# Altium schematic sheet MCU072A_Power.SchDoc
size 431 x 279 mm; Date: Not shown in title block; ApprovedBy: Not shown in title block; CheckedBy: Not shown in title block; Author: Not shown in title block; CompanyName: Not shown in title block; DrawnBy: Cody Watkins; Engineer: Not shown in title block; Organization: Not shown in title block; Address1: Not shown in title block; Address2: Not shown in title block; Address3: Not shown in title block; Address4: Not shown in title block; DocumentNumber: 3; Revision: Use project parameter SCH_Rev; SheetNumber: 3; SheetTotal: 7; PageSetup: Record=PageOptions¦CenterHorizontal=True¦CenterVertical=True¦PrintScale=1.00¦XCorrection=1.00¦YCorrection=1.00¦PrintKind=0¦BorderSize=5000000¦LeftOffset=0¦BottomOffset=0¦Orientation=2¦PaperLength=1000¦PaperWidth=1000¦Scale=100¦PaperSource=15¦PrintQuality=600¦MediaType=1¦DitherType=10¦PaperKind=Letter¦PrintScaleMode=1
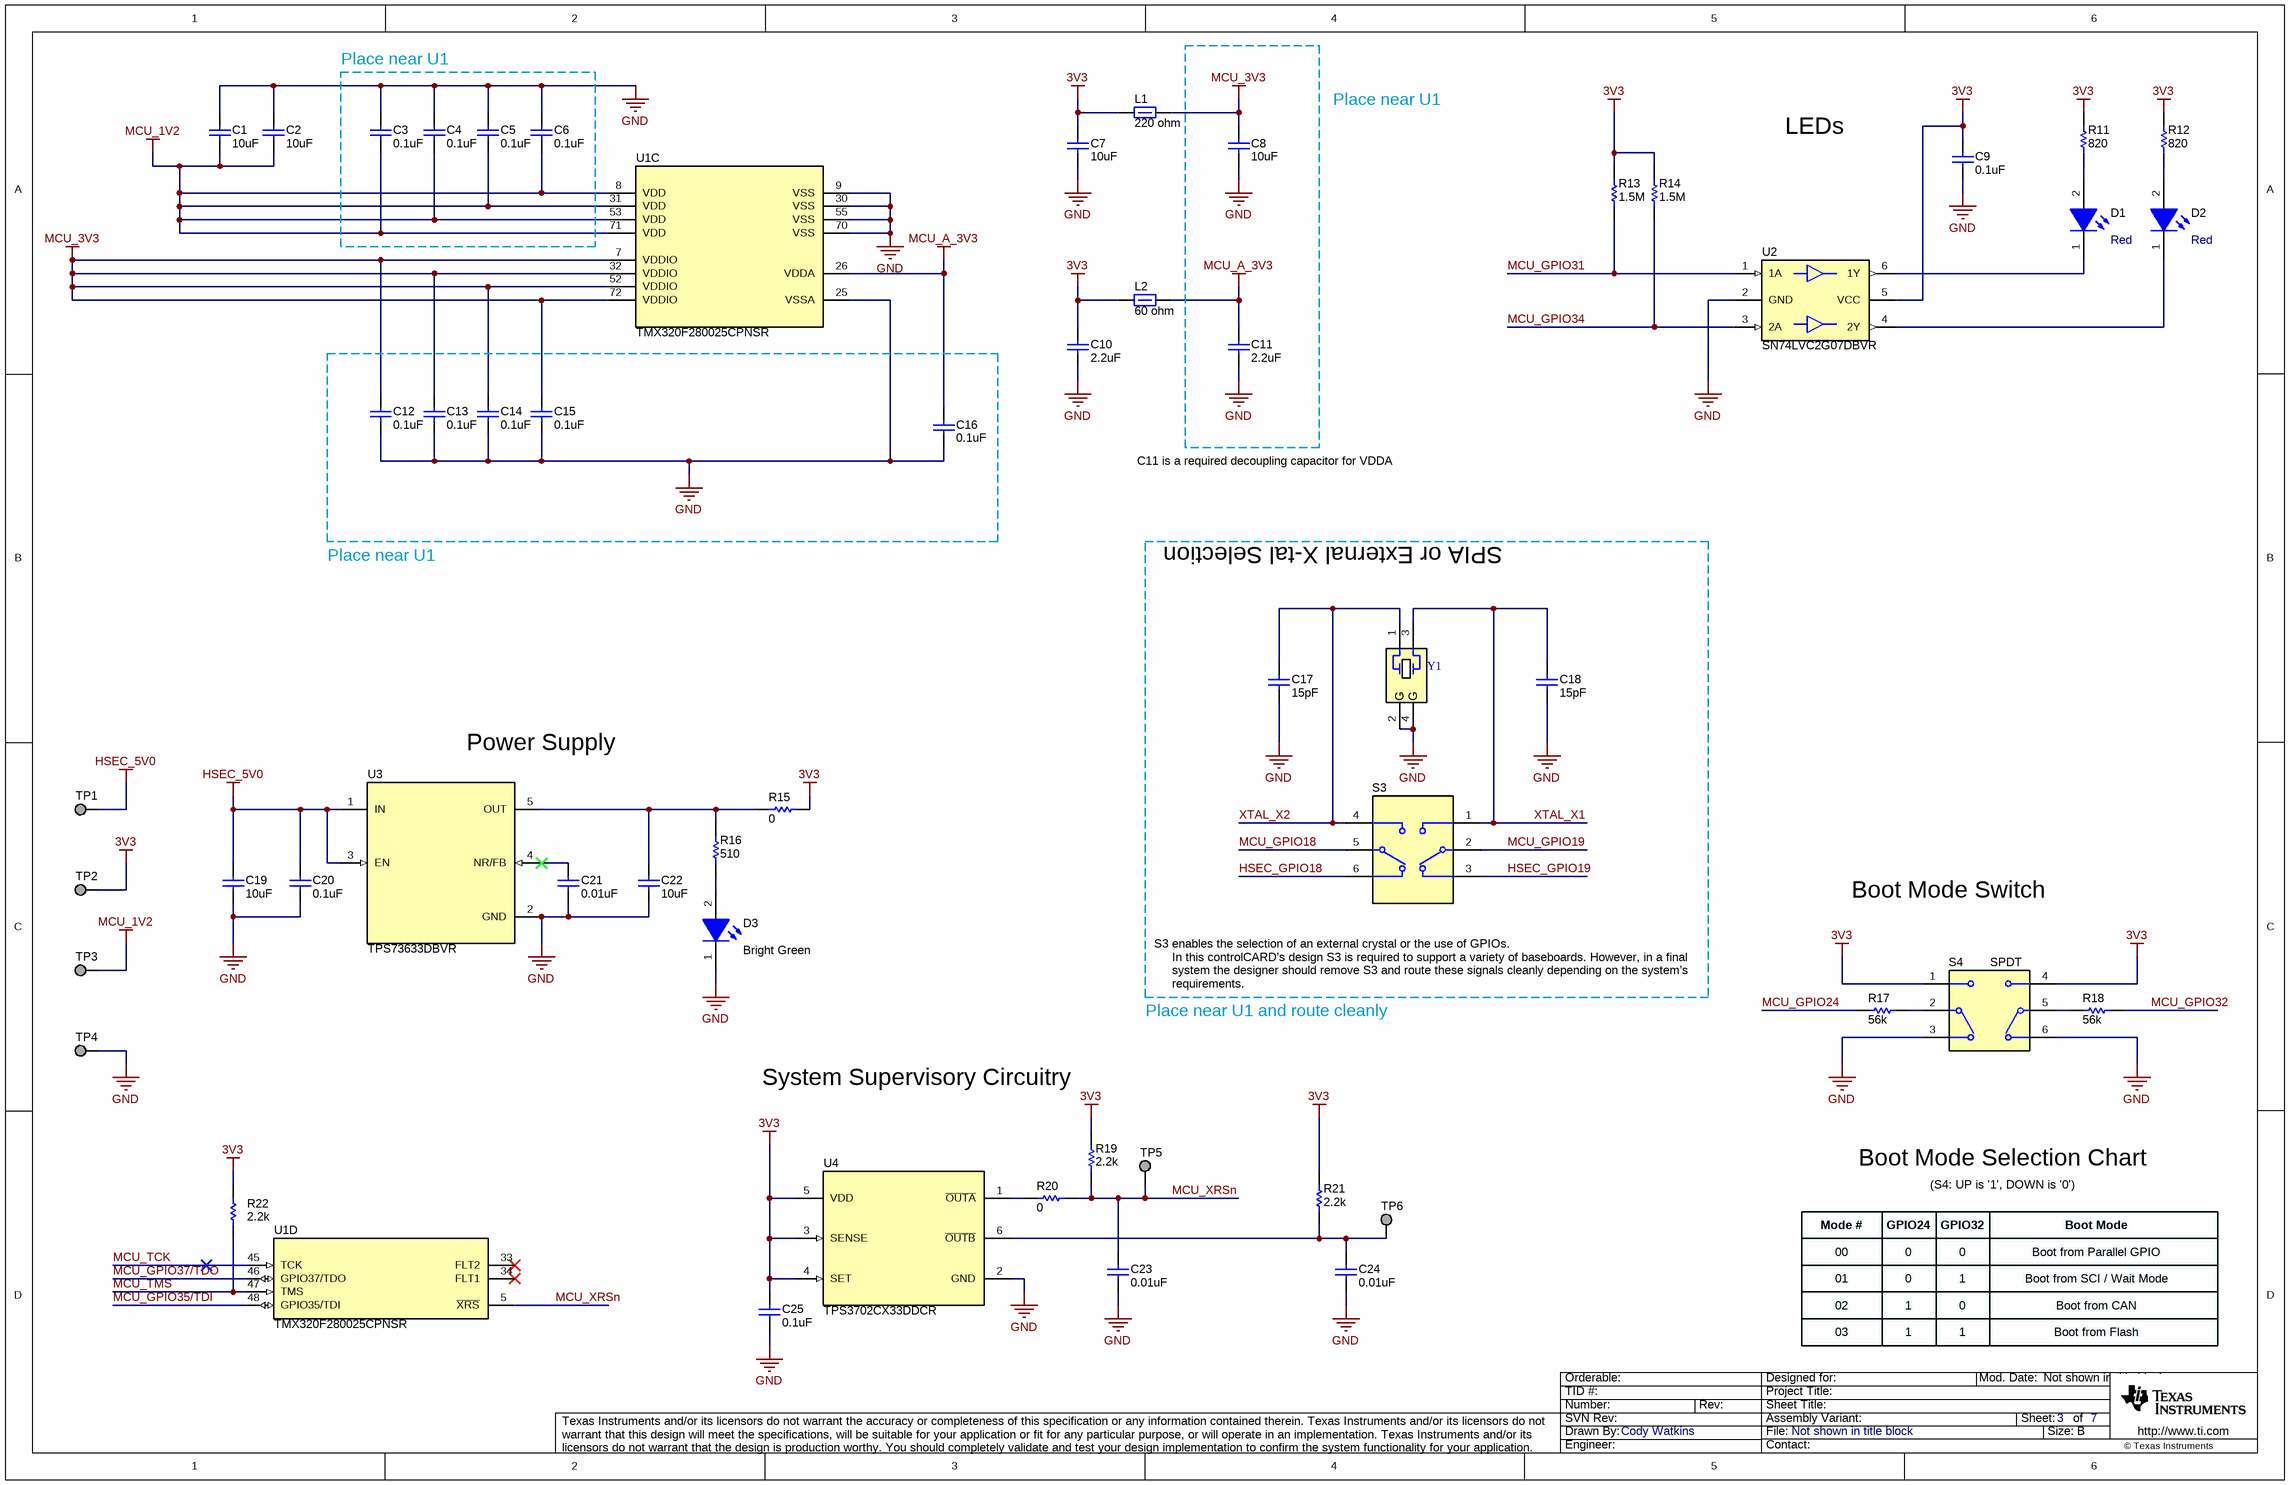
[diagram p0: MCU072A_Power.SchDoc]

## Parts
C1  ValueDisplayed: 10uF  [0603]  (hidden comment: GRM188R61A106ME69D)
C2  ValueDisplayed: 10uF  [0603]  (hidden comment: GRM188R61A106ME69D)
C3  ValueDisplayed: 0.1uF  [0402]  (hidden comment: 885012105010)
C4  ValueDisplayed: 0.1uF  [0402]  (hidden comment: 885012105010)
C5  ValueDisplayed: 0.1uF  [0402]  (hidden comment: 885012105010)
C6  ValueDisplayed: 0.1uF  [0402]  (hidden comment: 885012105010)
C7  ValueDisplayed: 10uF  [0805_HV]  (hidden comment: LMK212ABJ106KG-T)
C8  ValueDisplayed: 10uF  [0603]  (hidden comment: GRM188R61A106ME69D)
C9  ValueDisplayed: 0.1uF  [0402]  (hidden comment: 885012105010)
C10  ValueDisplayed: 2.2uF  [0603]  (hidden comment: CGA3E3X5R1A225K080AB)
C11  ValueDisplayed: 2.2uF  [0603]  (hidden comment: CGA3E3X5R1A225K080AB)
C12  ValueDisplayed: 0.1uF  [0402]  (hidden comment: 885012105010)
C13  ValueDisplayed: 0.1uF  [0402]  (hidden comment: 885012105010)
C14  ValueDisplayed: 0.1uF  [0402]  (hidden comment: 885012105010)
C15  ValueDisplayed: 0.1uF  [0402]  (hidden comment: 885012105010)
C16  ValueDisplayed: 0.1uF  [0402]  (hidden comment: 885012105010)
C17  ValueDisplayed: 15pF  [0402]  (hidden comment: 885012005056)
C18  ValueDisplayed: 15pF  [0402]  (hidden comment: 885012005056)
C19  ValueDisplayed: 10uF  [0603]  (hidden comment: GRM188R61A106ME69D)
C20  ValueDisplayed: 0.1uF  [0402]  (hidden comment: 885012105010)
C21  ValueDisplayed: 0.01uF  [0402]  (hidden comment: 0402ZC103KAT2A)
C22  ValueDisplayed: 10uF  [0603]  (hidden comment: GRM188R61A106ME69D)
C23  ValueDisplayed: 0.01uF  [0402]  (hidden comment: 0402ZC103KAT2A)
C24  ValueDisplayed: 0.01uF  [0402]  (hidden comment: 0402ZC103KAT2A)
C25  ValueDisplayed: 0.1uF  [0402]  (hidden comment: 885012105010)
D1  value Red  [WL-SMCW_RED_0805]  (hidden comment: 150080SS75000)
D2  value Red  [WL-SMCW_RED_0805]  (hidden comment: 150080SS75000)
D3  value Bright Green  [WL-SMCW_Green_0805]  (hidden comment: 150080VS75000)
L1  value 220 ohm  [0805_HV]  (hidden comment: BLM21PG221SN1D)
L2  value 60 ohm  [0805_HV]  (hidden comment: BKP2125HS600-T)
R11  ValueDisplayed: 820  [0402]  (hidden comment: CRCW0402820RJNED)
R12  ValueDisplayed: 820  [0402]  (hidden comment: CRCW0402820RJNED)
R13  ValueDisplayed: 1.5M  [0402]  (hidden comment: CRCW04021M50JNED)
R14  ValueDisplayed: 1.5M  [0402]  (hidden comment: CRCW04021M50JNED)
R15  ValueDisplayed: 0  [0805_HV]  (hidden comment: CRCW08050000Z0EA)
R16  ValueDisplayed: 510  [0402]  (hidden comment: CRCW0402510RJNED)
R17  ValueDisplayed: 56k  [0402]  (hidden comment: CRCW040256K0JNED)
R18  ValueDisplayed: 56k  [0402]  (hidden comment: CRCW040256K0JNED)
R19  ValueDisplayed: 2.2k  [0402]  (hidden comment: CRCW04022K20JNED)
R20  ValueDisplayed: 0  [0402]  (hidden comment: CRCW04020000Z0ED)
R21  ValueDisplayed: 2.2k  [0402]  (hidden comment: CRCW04022K20JNED)
R22  ValueDisplayed: 2.2k  [0402]  (hidden comment: CRCW04022K20JNED)
S3  CAS-220TA  [SW_CAS-220TA]  (value not drawn)
S4  Circuit: SPDT  [SW_CAS-D20TA]  (hidden comment: CAS-D20TA)
TP1  TESTPOINT  [TP_50MIL-25MILHOLE]  (value not drawn)  (no BOM)
TP2  TESTPOINT  [TP_50MIL-25MILHOLE]  (value not drawn)  (no BOM)
TP3  TESTPOINT  [TP_50MIL-25MILHOLE]  (value not drawn)  (no BOM)
TP4  TESTPOINT  [TP_50MIL-25MILHOLE]  (value not drawn)  (no BOM)
TP5  TESTPOINT  [TP_50MIL-25MILHOLE]  (value not drawn)  (no BOM)
TP6  TESTPOINT  [TP_50MIL-25MILHOLE]  (value not drawn)  (no BOM)
U1  TMX320F280025CPNSR  [PN0080A_N]  (parts C,D of 4)
U2  SN74LVC2G07DBVR  [DBV0006A_N]
U3  TPS73633DBVR  [DBV0005A_N]
U4  TPS3702CX33DDCR  [DDC0006A_N]
Y1  ECS-200-18-30B-AGN-TR  [ECS_ECX-53B]  (value not drawn)

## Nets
3V3: C7.2 C9.1 C10.2 C25.1 L1.1 L2.1 R11.2 R12.2 R13.2 R14.2 R15.2 R19.2 R21.2 R22.2 S4.1 S4.4 TP2.1 U2.5(VCC) U4.3(SENSE) U4.4(SET) U4.5(VDD)
GND: C1.2 C2.2 C3.1 C4.1 C5.1 C6.1 C7.1 C8.2 C9.2 C10.1 C11.1 C12.2 C13.2 C14.2 C15.2 C16.2 C17.2 C18.2 C19.2 C20.2 C21.1 C22.1 C23.1 C24.1 C25.2 D3.1(K) S4.3 S4.6 TP4.1 U1.9(VSS) U1.25(VSSA) U1.30(VSS) U1.55(VSS) U1.70(VSS) U2.2(GND) U3.2(GND) U4.2(GND) Y1.2(GND) Y1.4(GND)
HSEC_5V0: C19.1 C20.1 TP1.1 U3.1(IN) U3.3(EN)
MCU_1V2: C1.1 C2.1 C3.2 C4.2 C5.2 C6.2 TP3.1 U1.8(VDD) U1.31(VDD) U1.53(VDD) U1.71(VDD)
MCU_3V3: C8.1 C12.1 C13.1 C14.1 C15.1 L1.2 U1.7(VDDIO) U1.32(VDDIO) U1.52(VDDIO) U1.72(VDDIO)
MCU_A_3V3: C11.2 C16.1 L2.2 U1.26(VDDA)
HSEC_GPIO18: S3.6
HSEC_GPIO19: S3.3
MCU_GPIO18: S3.5
MCU_GPIO19: S3.2
MCU_GPIO24: R17.2
MCU_GPIO31: R13.1 U2.1(1A)
MCU_GPIO32: R18.1
MCU_GPIO34: R14.1 U2.3(2A)
MCU_GPIO35/TDI: U1.48(GPIO35/TDI)
MCU_GPIO37/TDO: U1.46(GPIO37/TDO)
MCU_TCK: U1.45(TCK)
MCU_TMS: R22.1 U1.47(TMS)
MCU_XRSn: C23.2 R19.1 R20.2 TP5.1 U1.5(~{XRS})
XTAL_X1: C18.1 S3.1 Y1.3
XTAL_X2: C17.1 S3.4 Y1.1
NetC21_2: C21.2 U3.4(NR/FB)
NetC22_2: C22.2 R15.1 R16.2 U3.5(OUT)
NetC24_2: C24.2 R21.1 TP6.1 U4.6(~{OUTB})
NetD1_1: D1.1(K) U2.6(1Y)
NetD1_2: D1.2(A) R11.1
NetD2_1: D2.1(K) U2.4(2Y)
NetD2_2: D2.2(A) R12.1
NetD3_2: D3.2(A) R16.1
NetR17_1: R17.1 S4.2(C)
NetR18_2: R18.2 S4.5(C)
NetR20_1: R20.1 U4.1(~{OUTA})

Not connected (* = marked no-connect by the designer): U1 33(FLT2)* 34(FLT1)*

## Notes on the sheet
- Place near U1
- LEDs
- C11 is a required decoupling capacitor for VDDA
- SPIA or External X-tal Selection
- Power Supply
- Boot Mode Switch
- In this controlCARD’s design S3 is required to support a variety of baseboards. However, in a final
- system the designer should remove S3 and route these signals cleanly depending on the system’s
- S3 enables the selection of an external crystal or the use of GPIOs.
- Place near U1 and route cleanly
- requirements.
- System Supervisory Circuitry
- Boot Mode Selection Chart
- Mode #
- GPIO24
- GPIO32
- (S4: UP is '1', DOWN is '0')
- Boot Mode
- 00
- 01
- 02
- 0
- 1
- Boot from Parallel GPIO
- Boot from SCI / Wait Mode
- Boot from CAN
- 03
- Boot from Flash

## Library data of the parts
C1 C2 C8 C19 C22 = CMP-0007318-5: CAP, CERM, 10 uF, 10 V, +/- 20%, X5R, 0603; Manufacturer: MuRata; Polarized: N; Value: 10uF; U/M: EA; Cap_F: 10µF; Value1: Unknown; VDC_V: 10V; TaMin_C: -55°C; TaMax_C: 85°C; AEC Category: Q200; SizeArea_mm2: 1.28; SizeAreaWB_mm2: 4.68; SizeX_mm: 1.6; SizeY_mm: 0.8; SizeZ_mm: 1
C3-C6 C12-C16 = CMP-0006221-2: CAP, CERM, 0.1 uF, 10 V, +/- 20%, X5R, 0402; Manufacturer: Wurth Elektronik; Polarized: N; Value: 0.1uF; U/M: EA; Cap_F: 100nF; Value1: Unknown; VDC_V: 10V; TaMin_C: -55°C; TaMax_C: 85°C; SizeArea_mm2: 0.5; SizeAreaWB_mm2: 3; SizeX_mm: 1; SizeZ_mm: 0.6; AEC Category: Q200
C7 = CMP-0008395-2: CAP, CERM, 10 uF, 10 V, +/- 10%, X5R, 0805; Manufacturer: Taiyo Yuden; Polarized: N; Value: 10uF; U/M: EA; Cap_F: 10µF; Value1: Unknown; VDC_V: 10V; TaMin_C: -55°C; TaMax_C: 85°C; Cap_Case: 0805; AEC Category: Q200; SizeArea_mm2: 2.5; SizeAreaWB_mm2: 6.75; SizeX_mm: 2; SizeY_mm: 1.25; SizeZ_mm: 1.45
C9 C20 C25 = CMP-0006221-2: CAP, CERM, 0.1 uF, 10 V, +/- 20%, X5R, 0402; Manufacturer: Wurth Elektronik; Polarized: N; Value: 0.1uF; U/M: EA; Cap_F: 100nF; Value1: Unknown; VDC_V: 10V; TaMin_C: -55°C; TaMax_C: 85°C; AEC Category: Q200; SizeArea_mm2: 0.5; SizeAreaWB_mm2: 3; SizeX_mm: 1; SizeZ_mm: 0.6
C10 C11 = CMP-0007091-5: CAP, CERM, 2.2 uF, 10 V, +/- 10%, X5R, AEC-Q200 Grade 3, 0603; Manufacturer: TDK; Polarized: N; Value: 2.2uF; U/M: EA; Cap_F: 2.2µF; Value1: Unknown; VDC_V: 10V; TaMin_C: -55°C; TaMax_C: 85°C; AEC Category: Q200; AEC Qualified: Y; AEC Grade: 3; SizeArea_mm2: 1.28; SizeAreaWB_mm2: 4.68; SizeX_mm: 1.6; SizeY_mm: 0.8; SizeZ_mm: 1
C17 C18 = CMP-0006216-2: CAP, CERM, 15 pF, 50 V, +/- 5%, C0G/NP0, 0402; Manufacturer: Wurth Elektronik; Polarized: N; Value: 15pF; U/M: EA; Value1: Unknown; VDC_V: 50V; TaMin_C: -55°C; TaMax_C: 125°C; AEC Category: Q200; SizeArea_mm2: 0.5; SizeAreaWB_mm2: 3; SizeX_mm: 1; SizeZ_mm: 0.6
C21 C23 C24 = CMP-0006203-2: CAP, CERM, 0.01 uF, 10 V, +/- 10%, X7R, 0402; Manufacturer: AVX; Polarized: N; Value: 0.01uF; U/M: EA; Cap_F: 10nF; Value1: Unknown; VDC_V: 10V; TaMin_C: -55°C; TaMax_C: 125°C; AEC Category: Q200; SizeArea_mm2: 0.5; SizeAreaWB_mm2: 3; SizeX_mm: 1; SizeZ_mm: 0.6
D1 D2 = CMP-0002951-3: LED, Red, SMD; Manufacturer: Wurth Elektronik; Type: AlInGaP; Vf_V: 1.9V; Io_A: 30mA; Vr_V: 5V; Ir_A: 25µA; Tjmax_C: 85°C; Power_TotalModule: 72mW; Value1: 0.072W; Angle: 140
D3 = CMP-0002960-2: LED, Bright Green, SMD; Manufacturer: Wurth Elektronik; Type: AlInGaP; Vf_V: 2V; Io_A: 20mA; Vr_V: 5V; Tjmax_C: 85°C; Power_TotalModule: 72mW; Value1: 0.072W; Angle: 140; U/M: EA
L1 = CMP-0003363-1: Ferrite Bead, 220 ohm @ 100 MHz, 2 A, 0805; Manufacturer: MuRata; Imax_A: 2A; DCR_ohm: 0.045; Value1: 0.045 ohm; ZTyp@100MHz_Ohm: 220; SizeArea_mm2: 2.5; SizeAreaWB_mm2: 6.75; SizeX_mm: 2; SizeY_mm: 1.25; SizeZ_mm: 1.45
L2 = CMP-0003306-1: Ferrite Bead, 60 ohm @ 100 MHz, 3 A, 0805; Manufacturer: Taiyo Yuden; Imax_A: 3A; DCR_ohm: 0.025; Value1: 0.025 ohm; ZTyp@100MHz_Ohm: 60; SizeArea_mm2: 2.5; SizeAreaWB_mm2: 6.75; SizeX_mm: 2; SizeY_mm: 1.25; SizeZ_mm: 1.45
R11 R12 = CMP-0026979-3: RES, 820, 5%, 0.063 W, AEC-Q200 Grade 0, 0402; Manufacturer: Vishay-Dale; Power_W: 63mW; TempCo: 200 ppm/C; Value_Code: 820R; Value: 820; EIA_Code: E24; SizeX_mm: 1; SizeY_mm: 0.5; SizeZ_mm: 0.6; Value2: 0.063W; AEC Qualified: Y; VDC_V: 50V; AEC Category: Q200; AEC Grade: 0
R13 R14 = CMP-0026863-2: RES, 1.5 M, 5%, 0.063 W, AEC-Q200 Grade 0, 0402; Manufacturer: Vishay-Dale; Power_W: 63mW; TempCo: 200 ppm/C; Value_Code: 1M50; Value: 1.5Meg; EIA_Code: E24; SizeX_mm: 1; SizeY_mm: 0.5; SizeZ_mm: 0.6; Value2: 0.063W; AEC Qualified: Y; VDC_V: 50V; AEC Category: Q200; AEC Grade: 0
R15 = CMP-0020442-3: RES, 0, 5%, 0.125 W, AEC-Q200 Grade 0, 0805; Manufacturer: Vishay-Dale; Value: 0; Value_Code: 0000; Power_W: 125mW; Value2: 0.125W; VDC_V: 150V; TempCo: 200 ppm/C; EIA_Code: E24; AEC Category: Q200; AEC Qualified: Y; SizeArea_mm2: 2.5; SizeX_mm: 2; SizeY_mm: 1.25; SizeZ_mm: 1.45
R16 = CMP-0026944-3: RES, 510, 5%, 0.063 W, AEC-Q200 Grade 0, 0402; Manufacturer: Vishay-Dale; Power_W: 63mW; TempCo: 200 ppm/C; Value_Code: 510R; Value: 510; EIA_Code: E24; SizeX_mm: 1; SizeY_mm: 0.5; SizeZ_mm: 0.6; Value2: 0.063W; AEC Qualified: Y; VDC_V: 50V; AEC Category: Q200; AEC Grade: 0
R17 R18 = CMP-0026949-3: RES, 56 k, 5%, 0.063 W, AEC-Q200 Grade 0, 0402; Manufacturer: Vishay-Dale; Value: 56k; Value_Code: 56k0; Power_W: 63mW; Value2: 0.063W; VDC_V: 50V; TempCo: 200 ppm/C; EIA_Code: E24; AEC Category: Q200; AEC Qualified: Y; AEC Grade: 0; SizeArea_mm2: 0.5; SizeX_mm: 1; SizeZ_mm: 0.6
R19 R21 R22 = CMP-0026890-5: RES, 2.2 k, 5%, 0.063 W, AEC-Q200 Grade 0, 0402; Manufacturer: Vishay-Dale; Value: 2.2k; Value_Code: 2k20; Power_W: 63mW; Value2: 0.063W; VDC_V: 50V; TempCo: 200 ppm/C; EIA_Code: E24; AEC Category: Q200; AEC Qualified: Y; AEC Grade: 0; SizeArea_mm2: 0.5; SizeX_mm: 1; SizeZ_mm: 0.6
R20 = CMP-0026822-3: RES, 0, 5%, 0.063 W, AEC-Q200 Grade 0, 0402; Manufacturer: Vishay-Dale; Value: 0; Value_Code: 0000; Power_W: 63mW; Value2: 0.063W; VDC_V: 50V; TempCo: 200 ppm/C; SizeArea_mm2: 0.5; SizeX_mm: 1; SizeZ_mm: 0.6; EIA_Code: E24; AEC Category: Q200; AEC Qualified: Y
S3 = CMP-0002123-2: SLIDE SWITCH DPDT  .1A, SMT; Manufacturer: Copal Electronics; CurrentRating_mA: 100A; SwitchFunction: On-On; VDC_V: 6V; PositionCount: 2
S4 = CMP-0002233-1: Switch, Dual SPDT,  2 Pos, 0.1A, 6VDC, SMD; Manufacturer: Copal Electronics; VDC_V: 6V; SwitchFunction: On-On; PositionCount: 2; CurrentRating_mA: 100A
TP1-TP6 = CMP-0078143-3: TEST POINT.  No entry in BOM.
U1 = CMP-0750188-2: TMX320F280025CPNSR, PN0080A (LQFP-80); Alternate Manufacturer: Texas Instruments; SizeY_mm: 14; CompType: IC; AEC Category: Q200; AEC Qualified: N; SizeAreaWB_mm2: 256; SizeArea_mm2: 196; SizeZ_mm: 1.6
U2 = CMP-0051789-2: Dual Buffer/Driver with Open-Drain Output, DBV0006A, LARGE T&R; Manufacturer: Texas Instruments; 3-State Output: No; Bits(#): 2; F @ Nom Voltage(Max)(Mhz): 150; ICC @ Nom Voltage(Max)(mA): 0.01; Input Type: CMOS/TTL; Logic: True; Output Drive (IOL/IOH)(Max)(mA): 32/-32; Output Type: CMOS; Rating: Catalog; Sub-Family: Inverting Buffer/Driver; Technology Family: LVC; tpd @ Nom Voltage(Max)(ns): 8.6,4.4,3.7,2.9; VCC(Max)(V): 5.5; VCC(Min)(V): 1.65; Voltage(Nom)(V): 1.8,2.5,3.3,5; AEC Category: Q200; AEC Qualified: N; CompType: IC; Green_Lifecycle: Active; Green_REACh: Passed; SizeArea_mm2: 8.12; SizeAreaWB_mm2: 14.82; SizeX_mm: 2.8; SizeY_mm: 2.9; SizeZ_mm: 1.45
U3 = CMP-0036866-2: Single Output Low Noise LDO, 400 mA, Fixed 3.3 V Output, 1.7 to 5.5 V Input, with Reverse Current Protection, 5-pin SOT-23 (DBV), -40 to 85 degC, Green (RoHS & no Sb/Br); Manufacturer: Texas Instruments; Alternate PartNumber: TPS73633DBVT; Accuracy(%): 1; Fixed Output Options(V): 3.3; Iout(Max)(A): 0.4; Iq(Typ)(mA): 0.3; Rating: Catalog; SubFamily: Single Channel LDO; Vdo(Typ)(mV): 75; Vin(Max)(V): 5.5; Vin(Min)(V): 1.7; AEC Category: Q200; AEC Qualified: N; CompType: IC; Green_Lifecycle: Active; Green_REACh: Passed; SizeArea_mm2: 8.12; SizeAreaWB_mm2: 14.82; SizeX_mm: 2.8; SizeY_mm: 2.9; SizeZ_mm: 1.45
U4 = CMP-0067340-3: High-Accuracy, Fixed-Threshold OV/UV Monitor, DDC0006A (SOT-23-T-6); Alternate PartNumber: TPS3702CX33DDCT; Manufacturer: Texas Instruments; SizeZ_mm: 0.87; SizeX_mm: 1.65; SizeY_mm: 2.95; SizeArea_mm2: 4.8675; CompType: IC; SizeAreaWB_mm2: 10.4675; AEC Category: Q200
Y1 = CMP-0080365-2: Crystal, 20 MHz, 25 ppm, 18 pF, SMD; Manufacturer: ECS Inc.; Frequency Stability: 30 ppm; AEC Qualified: N; Frequency Tolerance: 25 ppm; AEC Category: Q200; TaMax_C: 85°C; Frequency_Fixed: 20MHz; TaMin_C: -40°C; Load Capacitance: 18 pF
